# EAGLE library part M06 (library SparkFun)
Header 6 Standard 6-pin 0.1" header. Use with straight break away headers (SKU : PType-HD), right angle break away headers (PType-HD-RightAngle), swiss pins (PType-30F), machine pins (PType-MP), and female headers (PType-FH). Molex polarized connector foot print use with SKU : Con-Hdr with associated crimp pins and housings.
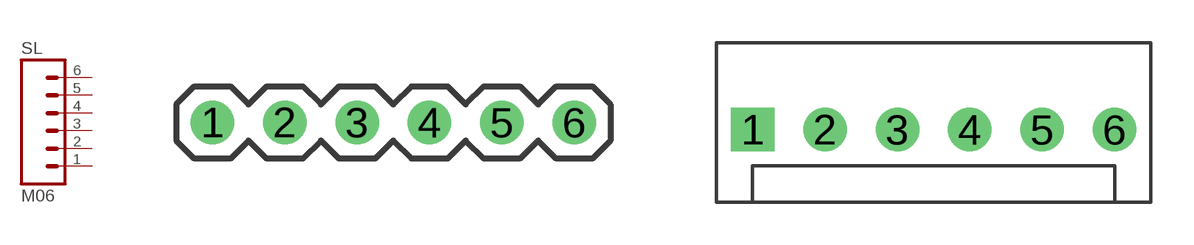
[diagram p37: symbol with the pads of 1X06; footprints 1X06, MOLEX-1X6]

Designator prefix SL

## M06SIP  [1X06]
1  1  pas
2  2  pas
3  3  pas
4  4  pas
5  5  pas
6  6  pas

## M06POL  [MOLEX-1X6]
Pads as for 1X06

## Footprint 1X06 (pad centres in mm)
drill 1.016 round: 1 0,0; 2 2.54,0; 3 5.08,0; 4 7.62,0; 5 10.16,0; 6 12.7,0

## Footprint MOLEX-1X6 (pad centres in mm)
drill 1.016 square: 1 0,0
drill 1.016 round: 2 2.54,0; 3 5.08,0; 4 7.62,0; 5 10.16,0; 6 12.7,0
